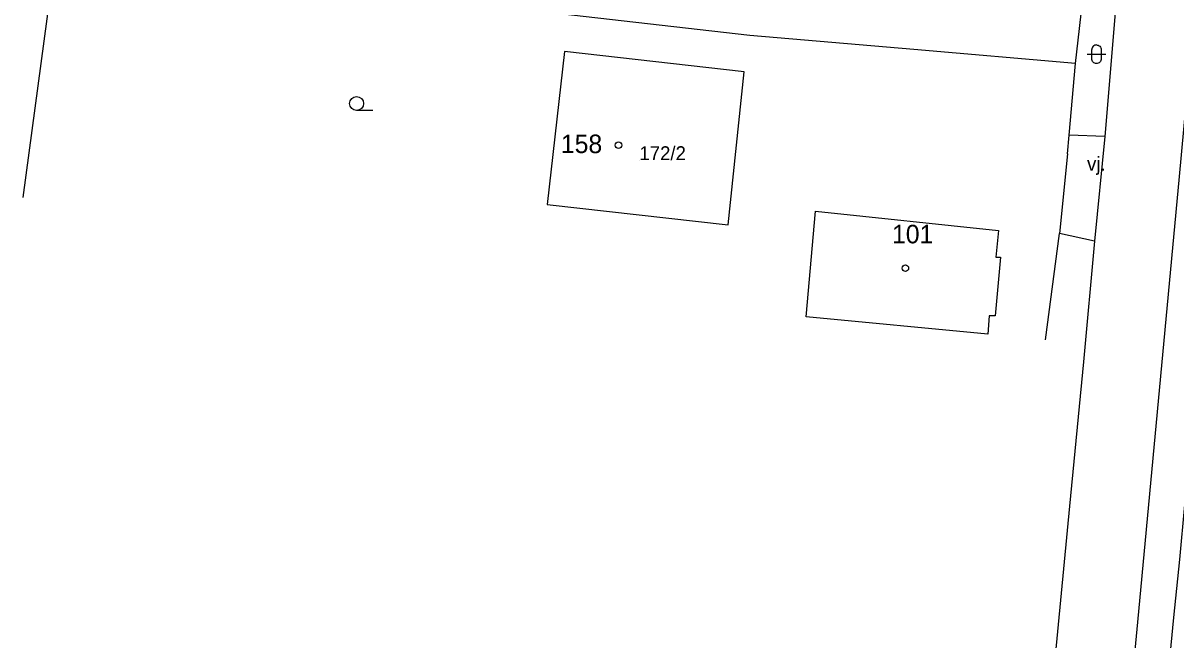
# Model space of a CAD drawing. Extents: x -836739 to -835945, y -1070775 to -1070126.
# Drawn here: x -836595.2 to -836533, y -1070547.4 to -1070514.1 of the extents above; entities that cross this region are included whole.
import ezdxf

# ---------------------------------------------------------------- set-up
doc = ezdxf.new("R2010")
doc.units = 0
for name, color, linetype in [('BodPole_mer', 7, 'Continuous'), ('Budovy_hranice', 7, 'Continuous'), ('Budovy_kody', 7, 'Continuous'), ('Doprava_hranice', 7, 'Continuous'), ('Doprava_kody', 7, 'Continuous'), ('OstPloch_kody', 7, 'Continuous'), ('RuianAdr_popis', 7, 'Continuous'), ('RuianPar_popis', 7, 'Continuous'), ('Stavby_linie', 7, 'Continuous')]:
    doc.layers.add(name, color=color, linetype=linetype)

msp = doc.modelspace()

# ---------------------------------------------------------------- linework, layer by layer
at = {"layer": 'BodPole_mer'}
for p, q in [((-836555.98, -1070514.79), (-836555.98, -1070514.79)), ((-836566, -1070515.65), (-836566, -1070515.65)), ((-836547.13, -1070515.54), (-836547.13, -1070515.54)), ((-836556.29, -1070516.75), (-836556.29, -1070516.75)), ((-836538.4, -1070516.3), (-836538.4, -1070516.3)), ((-836538.74, -1070520.16), (-836538.74, -1070520.16)), ((-836536.82, -1070520.24), (-836536.82, -1070520.24)), ((-836538.83, -1070521.16), (-836538.83, -1070521.16)), ((-836552.44, -1070524.27), (-836552.44, -1070524.27)), ((-836557.16, -1070525.01), (-836557.16, -1070525.01)), ((-836542.56, -1070525.31), (-836542.56, -1070525.31)), ((-836539.26, -1070525.47), (-836539.26, -1070525.47)), ((-836537.38, -1070525.89), (-836537.38, -1070525.89)), ((-836542.71, -1070526.74), (-836542.71, -1070526.74)), ((-836542.46, -1070526.75), (-836542.46, -1070526.75))]:
    msp.add_line(p, q, dxfattribs=at)
at = {"layer": 'Budovy_hranice'}
for points in [[(-836566, -1070515.65), (-836566.93, -1070523.91), (-836557.16, -1070525.01), (-836556.29, -1070516.75), (-836566, -1070515.65)], [(-836552.95, -1070529.96), (-836552.44, -1070524.27), (-836542.56, -1070525.31), (-836542.71, -1070526.74), (-836542.46, -1070526.75), (-836542.75, -1070529.92), (-836543.06, -1070529.91), (-836543.14, -1070530.9), (-836552.95, -1070529.96)]]:
    msp.add_lwpolyline(points, dxfattribs=at)
at = {"layer": 'Budovy_kody'}
for centre in [(-836563.08, -1070520.7), (-836547.59, -1070527.34)]:
    msp.add_circle(centre, 0.175, dxfattribs=at)
at = {"layer": 'Doprava_hranice'}
for p, q in [((-836536.82, -1070520.24), (-836538.74, -1070520.16)), ((-836537.38, -1070525.89), (-836539.26, -1070525.47))]:
    msp.add_line(p, q, dxfattribs=at)
for points in [[(-836531.1, -1070469.82), (-836532.59, -1070473.19), (-836533.47, -1070481.32), (-836533.93, -1070486.76), (-836533.99, -1070488.23), (-836534.36, -1070493.24), (-836535.73, -1070507.97), (-836536.22, -1070513.12), (-836536.82, -1070520.24), (-836537.38, -1070525.89), (-836537.98, -1070532.4), (-836538.73, -1070540.19), (-836539.5, -1070548.26)], [(-836535.55, -1070551.78), (-836534.99, -1070545.87), (-836532.78, -1070522.39), (-836532.06, -1070514.59), (-836531.14, -1070504.66), (-836530.74, -1070499.84), (-836530.27, -1070494.21), (-836529.99, -1070490.91), (-836529.84, -1070489.08), (-836529.13, -1070478.74)]]:
    msp.add_lwpolyline(points, dxfattribs=at)
at = {"layer": 'OstPloch_kody'}
for p, q in [((-836537.52, -1070516.04), (-836537.52, -1070515.54)), ((-836537.02, -1070515.54), (-836537.02, -1070516.04)), ((-836537.77, -1070515.79), (-836536.77, -1070515.79)), ((-836576.345, -1070518.83), (-836577.22, -1070518.83))]:
    msp.add_line(p, q, dxfattribs=at)
for points in [[(-836537.27, -1070515.29), (-836537.315, -1070515.294), (-836537.362, -1070515.308), (-836537.407, -1070515.331), (-836537.447, -1070515.363), (-836537.479, -1070515.403), (-836537.502, -1070515.448), (-836537.516, -1070515.495), (-836537.52, -1070515.54)], [(-836537.27, -1070515.29), (-836537.225, -1070515.294), (-836537.178, -1070515.308), (-836537.133, -1070515.331), (-836537.093, -1070515.363), (-836537.061, -1070515.403), (-836537.038, -1070515.448), (-836537.024, -1070515.495), (-836537.02, -1070515.54)], [(-836537.27, -1070516.29), (-836537.315, -1070516.286), (-836537.362, -1070516.272), (-836537.407, -1070516.249), (-836537.447, -1070516.217), (-836537.479, -1070516.177), (-836537.502, -1070516.132), (-836537.516, -1070516.085), (-836537.52, -1070516.04)], [(-836537.02, -1070516.04), (-836537.024, -1070516.085), (-836537.038, -1070516.132), (-836537.061, -1070516.177), (-836537.093, -1070516.217), (-836537.133, -1070516.249), (-836537.178, -1070516.272), (-836537.225, -1070516.286), (-836537.27, -1070516.29)]]:
    msp.add_lwpolyline(points, dxfattribs=at)
msp.add_ellipse((-836577.22, -1070518.455), major_axis=(0.375, 0), ratio=0.999999, dxfattribs=at)
at = {"layer": 'RuianAdr_popis'}
for p, q in [((-836566.19, -1070521.13), (-836566.19, -1070521.13)), ((-836548.31, -1070526), (-836548.31, -1070526))]:
    msp.add_line(p, q, dxfattribs=at)
at = {"layer": 'RuianPar_popis'}
msp.add_line((-836561.95, -1070521.51), (-836561.95, -1070521.51), dxfattribs=at)
at = {"layer": 'Stavby_linie'}
for p in [(-836538.83, -1070521.16), (-836540.02, -1070531.21)]:
    msp.add_line(p, (-836539.26, -1070525.47), dxfattribs=at)
for points in [[(-836595.23, -1070523.53), (-836593.6, -1070511.46), (-836593.12, -1070507.61), (-836591.39, -1070493.82), (-836591.23, -1070492.73), (-836590.13, -1070485.13), (-836589.2, -1070477.29)], [(-836538.83, -1070521.16), (-836538.74, -1070520.16), (-836538.4, -1070516.3), (-836537.96, -1070512.33)], [(-836538.4, -1070516.3), (-836547.13, -1070515.54), (-836555.98, -1070514.79), (-836566.25, -1070513.62), (-836566.34, -1070513.61)], [(-836531.43, -1070528.31), (-836532.79, -1070543.06), (-836533.11, -1070546.2), (-836533.66, -1070551.8), (-836535.45, -1070569.74)]]:
    msp.add_lwpolyline(points, dxfattribs=at)

# ---------------------------------------------------------------- texts
at = {"layer": 'Doprava_kody'}
msp.add_text('vj.', height=0.75, dxfattribs=at).set_placement((-836537.78, -1070522.08))
at = {"layer": 'RuianAdr_popis'}
for s, p in [('158', (-836566.19, -1070521.13)), ('101', (-836548.31, -1070526))]:
    msp.add_text(s, height=1, dxfattribs=at).set_placement(p)
at = {"layer": 'RuianPar_popis'}
msp.add_text('172/2', height=0.75, dxfattribs=at).set_placement((-836561.95, -1070521.51))

doc.saveas('drawing.dxf')
